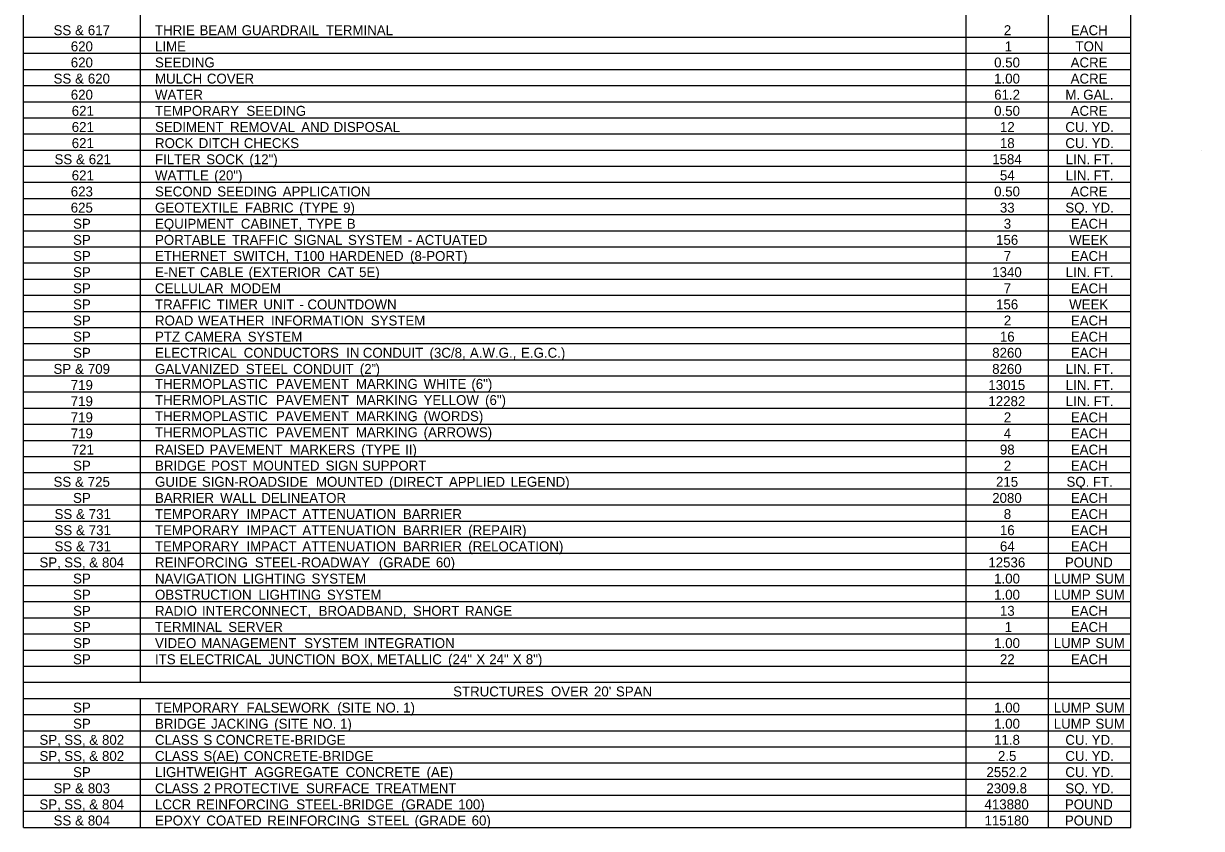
# Model space of a CAD drawing. Extents: x 107 to 7866, y 32 to 1473.
# Drawn here: x 6428 to 7140, y 67 to 553 of the extents above; entities that cross this region are included whole.
import ezdxf

# ---------------------------------------------------------------- set-up
doc = ezdxf.new("R2010")
doc.units = 0
doc.layers.add('Default', color=7, linetype='Continuous')

msp = doc.modelspace()

# ---------------------------------------------------------------- linework, layer by layer
at = {"layer": 'Default'}
for p, q in [((6427.83, 67.45), (6427.83, 1032.7)), ((6427.83, 67.45), (6427.83, 1032.7)), ((6498.52, 155.2), (6498.52, 1032.7)), ((6997.72, 67.45), (6997.72, 1032.7)), ((7047.45, 67.45), (7047.45, 1032.7)), ((7047.45, 155.2), (7047.45, 1032.7)), ((7097.17, 67.45), (7097.17, 1032.7)), ((6498.52, 340.45), (6498.52, 1003.45)), ((6997.72, 340.45), (6997.72, 1003.45)), ((6427.83, 545.2), (7097.17, 545.2)), ((6427.83, 535.45), (7097.17, 535.45)), ((6427.83, 525.7), (7097.17, 525.7)), ((6427.83, 515.95), (7097.17, 515.95)), ((6427.83, 506.2), (7097.17, 506.2)), ((6427.83, 496.45), (7097.17, 496.45)), ((6427.83, 486.7), (7097.17, 486.7)), ((6427.83, 476.95), (7097.17, 476.95)), ((7139.96, 476.49), (7139.96, 476.49)), ((6427.83, 467.2), (7097.17, 467.2)), ((6427.83, 457.45), (7097.17, 457.45)), ((6427.83, 447.7), (7097.17, 447.7)), ((6427.83, 437.95), (7097.17, 437.95)), ((6427.83, 428.2), (7097.17, 428.2)), ((6427.83, 418.45), (7097.17, 418.45)), ((6427.83, 408.7), (7097.17, 408.7)), ((6427.83, 398.95), (7097.17, 398.95)), ((6427.83, 389.2), (7097.17, 389.2)), ((6427.83, 379.45), (7097.17, 379.45)), ((6427.83, 369.7), (7097.17, 369.7)), ((6427.83, 359.95), (7097.17, 359.95)), ((6427.83, 350.2), (7097.17, 350.2)), ((6427.83, 340.45), (7097.17, 340.45)), ((6427.83, 330.7), (7097.17, 330.7)), ((6498.52, 330.7), (6997.72, 330.7)), ((6498.52, 301.45), (6498.52, 330.7)), ((6997.72, 330.7), (7097.17, 330.7)), ((6997.72, 155.2), (6997.72, 330.7)), ((6427.83, 320.95), (7097.17, 320.95)), ((6427.83, 311.2), (7097.17, 311.2)), ((6427.83, 301.45), (7097.17, 301.45)), ((6498.52, 155.2), (6498.52, 301.45)), ((6427.83, 291.7), (7097.17, 291.7)), ((6427.83, 281.95), (7097.17, 281.95)), ((6427.83, 272.2), (7097.17, 272.2)), ((6427.83, 262.45), (7097.17, 262.45)), ((6427.83, 252.7), (7097.17, 252.7)), ((6427.83, 242.95), (7097.17, 242.95)), ((6427.83, 233.2), (7097.17, 233.2)), ((6427.83, 223.45), (7097.17, 223.45)), ((6427.83, 213.7), (7097.17, 213.7)), ((6427.83, 203.95), (7097.17, 203.95)), ((6427.83, 194.2), (7097.17, 194.2)), ((6427.83, 184.45), (7097.17, 184.45)), ((6427.83, 174.7), (7097.17, 174.7)), ((6427.83, 164.95), (7097.17, 164.95)), ((6427.83, 155.2), (7097.17, 155.2)), ((7047.45, 155.2), (7097.17, 155.2)), ((6427.83, 145.45), (7097.17, 145.45)), ((6427.83, 145.45), (7097.17, 145.45)), ((6498.52, 67.45), (6498.52, 145.45)), ((6498.52, 67.45), (6498.52, 145.45)), ((6997.72, 67.45), (6997.72, 145.45)), ((7047.45, 67.45), (7047.45, 145.45)), ((6427.83, 135.7), (7097.17, 135.7)), ((6427.83, 125.95), (7097.17, 125.95)), ((6427.83, 116.2), (7097.17, 116.2)), ((6427.83, 106.45), (7097.17, 106.45)), ((6427.83, 96.7), (7097.17, 96.7)), ((6427.83, 86.95), (7097.17, 86.95)), ((6427.83, 77.2), (7097.17, 77.2)), ((6427.83, 67.45), (7097.17, 67.45))]:
    msp.add_line(p, q, dxfattribs=at)

# ---------------------------------------------------------------- texts
for s, p in [('SS', (6445.97, 546.4)), (' &', (6456.72, 546.4)), (' 617', (6464.45, 546.4)), ('THRIE', (6507.3, 546.4)), (' BEAM', (6532, 546.4)), (' GUARDRAIL', (6557.46, 546.4)), (' TERMINAL', (6608.4, 546.4)), ('2', (7020.47, 546.4)), ('EACH', (7061, 546.4)), ('620', (6456.39, 536.65)), ('LIME', (6507.3, 536.65)), ('1', (7021.02, 536.65)), ('TON', (7063.8, 536.65)), ('620', (6456.39, 526.9)), ('SEEDING', (6507.3, 526.9)), ('0.50', (7014.63, 526.9)), ('ACRE', (7060.88, 526.9)), ('SS', (6445.99, 517.15)), (' &', (6456.73, 517.15)), (' 620', (6464.46, 517.15)), ('MULCH', (6507.3, 517.15)), (' COVER', (6536.43, 517.15)), ('1.00', (7014.63, 517.15)), ('ACRE', (7060.88, 517.15)), ('620', (6456.39, 507.4)), ('WATER', (6507.3, 507.4)), ('61.2', (7014.65, 507.4)), ('M.', (7057.67, 507.4)), (' GAL.', (7066.25, 507.4)), ('621', (6456.96, 497.65)), ('TEMPORARY', (6507.3, 497.65)), (' SEEDING', (6560.34, 497.65)), ('0.50', (7014.63, 497.65)), ('ACRE', (7060.88, 497.65)), ('621', (6456.96, 487.9)), ('SEDIMENT', (6507.3, 487.9)), (' REMOVAL', (6550.45, 487.9)), (' AND', (6593.48, 487.9)), (' DISPOSAL', (6613.06, 487.9)), ('12', (7018.14, 487.9)), ('CU.', (7057.67, 487.9)), (' YD.', (7071.37, 487.9)), ('621', (6456.96, 478.15)), ('ROCK', (6507.3, 478.15)), (' DITCH', (6531.5, 478.15)), (' CHECKS', (6558.77, 478.15)), ('18', (7018.11, 478.15)), ('CU.', (7057.67, 478.15)), (' YD.', (7071.37, 478.15)), ('SS', (6446.56, 468.4)), (' &', (6457.3, 468.4)), (' 621', (6465.03, 468.4)), ('FILTER', (6507.3, 468.4)), (' SOCK', (6536.06, 468.4)), (' (12")', (6562.13, 468.4)), ('1584', (7013.47, 468.4)), ('LIN.', (7057.9, 468.4)), (' FT.', (7072.54, 468.4)), ('621', (6456.96, 458.65)), ('WATTLE', (6507.3, 458.65)), (' (20")', (6540.85, 458.65)), ('54', (7018.13, 458.65)), ('LIN.', (7057.9, 458.65)), (' FT.', (7072.54, 458.65)), ('623', (6456.38, 448.9)), ('SECOND', (6507.3, 448.9)), (' SEEDING', (6542.72, 448.9)), (' APPLICATION', (6582.26, 448.9)), ('0.50', (7014.63, 448.9)), ('ACRE', (7060.88, 448.9)), ('625', (6456.35, 439.15)), ('GEOTEXTILE', (6507.3, 439.15)), (' FABRIC', (6559.49, 439.15)), (' (TYPE', (6592.23, 439.15)), (' 9)', (6618.8, 439.15)), ('33', (7018.11, 439.15)), ('SQ.', (7057.67, 439.15)), (' YD.', (7071.38, 439.15)), ('SP', (6457.77, 429.4)), ('EQUIPMENT', (6507.3, 429.4)), (' CABINET,', (6556.97, 429.4)), (' TYPE', (6597.22, 429.4)), (' B', (6621, 429.4)), ('3', (7020.44, 429.4)), ('EACH', (7061, 429.4)), ('SP', (6457.77, 419.65)), ('PORTABLE', (6507.3, 419.65)), (' TRAFFIC', (6551.58, 419.65)), (' SIGNAL', (6588.97, 419.65)), (' SYSTEM', (6621.75, 419.65)), (' -', (6657.92, 419.65)), (' ACTUATED', (6662.78, 419.65)), ('156', (7015.78, 419.65)), ('WEEK', (7059.97, 419.65)), ('SP', (6457.77, 409.9)), ('ETHERNET', (6507.3, 409.9)), (' SWITCH,', (6552.31, 409.9)), (' T100', (6589.29, 409.9)), (' HARDENED', (6610.32, 409.9)), (' (8-PORT)', (6659.25, 409.9)), ('7', (7020.44, 409.9)), ('EACH', (7061, 409.9)), ('SP', (6457.77, 400.15)), ('E-NET', (6507.3, 400.15)), (' CABLE', (6532.28, 400.15)), (' (EXTERIOR', (6561.65, 400.15)), (' CAT', (6609.51, 400.15)), (' 5E)', (6628.44, 400.15)), ('1340', (7013.46, 400.15)), ('LIN.', (7057.9, 400.15)), (' FT.', (7072.54, 400.15)), ('SP', (6457.77, 390.4)), ('CELLULAR', (6507.3, 390.4)), (' MODEM', (6550.51, 390.4)), ('7', (7020.44, 390.4)), ('EACH', (7061, 390.4)), ('SP', (6457.77, 380.65)), ('TRAFFIC', (6507.3, 380.65)), (' TIMER', (6542.36, 380.65)), (' UNIT', (6570.65, 380.65)), (' COUNTDOWN', (6597.23, 380.65)), ('156', (7015.78, 380.65)), ('WEEK', (7059.97, 380.65)), (' -', (6592.37, 380.65)), ('SP', (6457.77, 370.9)), ('ROAD', (6507.3, 370.9)), (' WEATHER', (6531.07, 370.9)), (' INFORMATION', (6575.21, 370.9)), (' SYSTEM', (6635.53, 370.9)), ('2', (7020.47, 370.9)), ('EACH', (7061, 370.9)), ('SP', (6457.77, 361.15)), ('PTZ', (6507.3, 361.15)), (' CAMERA', (6522.92, 361.15)), (' SYSTEM', (6561.14, 361.15)), ('16', (7018.11, 361.15)), ('EACH', (7061, 361.15)), ('SP', (6457.77, 351.4)), ('ELECTRICAL', (6507.3, 351.4)), (' CONDUCTORS', (6558.71, 351.4)), (' IN', (6620.69, 351.4)), (' CONDUIT', (6630.71, 351.4)), (' (3C/8,', (6671.06, 351.4)), (' A.W.G.,', (6695.46, 351.4)), (' E.G.C.)', (6726.38, 351.4)), ('8260', (7013.46, 351.4)), ('EACH', (7061, 351.4)), ('SP', (6445.93, 341.65)), (' &', (6456.75, 341.65)), (' 709', (6464.48, 341.65)), ('GALVANIZED', (6507.3, 341.65)), (' STEEL', (6559.96, 341.65)), (' CONDUIT', (6588.55, 341.65)), (' (2', (6628.9, 341.65)), ('”', (6638.23, 341.65)), (')', (6640.65, 341.65)), ('8260', (7013.46, 341.65)), ('LIN.', (7057.9, 341.65)), (' FT.', (7072.54, 341.65)), ('719', (6456.37, 331.9)), ('THERMOPLASTIC', (6507.3, 332.58)), (' PAVEMENT', (6578.23, 332.58)), (' MARKING', (6626.52, 332.58)), (' WHITE', (6667.45, 332.58)), (' (6")', (6696.34, 332.58)), ('13015', (7011.1, 331.9)), ('LIN.', (7057.9, 331.9)), (' FT.', (7072.54, 331.9)), ('719', (6456.37, 322.15)), ('THERMOPLASTIC', (6507.3, 322.83)), (' PAVEMENT', (6578.23, 322.83)), (' MARKING', (6626.52, 322.83)), (' YELLOW', (6667.45, 322.83)), (' (6")', (6704.62, 322.83)), ('12282', (7011.15, 322.15)), ('LIN.', (7057.9, 322.15)), (' FT.', (7072.54, 322.15)), ('719', (6456.37, 312.4)), ('THERMOPLASTIC', (6507.3, 313.08)), (' PAVEMENT', (6578.23, 313.08)), (' MARKING', (6626.52, 313.08)), (' (WORDS)', (6667.45, 313.08)), ('2', (7020.47, 312.4)), ('EACH', (7061, 312.4)), ('719', (6456.37, 302.65)), ('THERMOPLASTIC', (6507.3, 303.33)), (' PAVEMENT', (6578.23, 303.33)), (' MARKING', (6626.52, 303.33)), (' (ARROWS)', (6667.45, 303.33)), ('4', (7020.46, 302.65)), ('EACH', (7061, 302.65)), (' (TYPE', (6629.7, 292.9)), (' II)', (6656.27, 292.9)), ('721', (6456.96, 292.9)), ('RAISED', (6507.3, 292.9)), (' PAVEMENT', (6538.06, 292.9)), (' MARKERS', (6586.35, 292.9)), ('98', (7018.11, 292.9)), ('EACH', (7061, 292.9)), ('SP', (6457.77, 283.15)), ('BRIDGE', (6507.3, 283.15)), (' POST', (6538.99, 283.15)), (' MOUNTED', (6563.98, 283.15)), (' SIGN', (6608.24, 283.15)), (' SUPPORT', (6630.38, 283.15)), ('2', (7020.47, 283.15)), ('EACH', (7061, 283.15)), ('SS', (6445.95, 273.4)), (' &', (6456.7, 273.4)), (' 725', (6464.43, 273.4)), ('GUIDE', (6507.3, 273.4)), (' SIGN-ROADSIDE', (6533.4, 273.4)), (' MOUNTED', (6602.36, 273.4)), (' (DIRECT', (6646.62, 273.4)), (' APPLIED', (6682.78, 273.4)), (' LEGEND)', (6720.07, 273.4)), ('215', (7015.76, 273.4)), ('SQ.', (7058.37, 273.4)), (' FT.', (7072.08, 273.4)), ('SP', (6457.77, 263.65)), ('BARRIER', (6507.3, 263.65)), (' WALL', (6544.45, 263.65)), (' DELINEATOR', (6569.31, 263.65)), ('2080', (7013.46, 263.65)), ('EACH', (7061, 263.65)), ('SS', (6446.56, 253.9)), (' &', (6457.3, 253.9)), (' 731', (6465.03, 253.9)), ('TEMPORARY', (6507.3, 253.9)), (' IMPACT', (6560.34, 253.9)), (' ATTENUATION', (6594.17, 253.9)), (' BARRIER', (6654.97, 253.9)), ('8', (7020.44, 253.9)), ('EACH', (7061, 253.9)), ('SS', (6446.56, 244.15)), (' &', (6457.3, 244.15)), (' 731', (6465.03, 244.15)), ('TEMPORARY', (6507.3, 244.15)), (' IMPACT', (6560.34, 244.15)), (' ATTENUATION', (6594.17, 244.15)), (' BARRIER', (6654.97, 244.15)), (' (REPAIR)', (6694.46, 244.15)), ('16', (7018.11, 244.15)), ('EACH', (7061, 244.15)), ('SS', (6446.56, 234.4)), (' &', (6457.3, 234.4)), (' 731', (6465.03, 234.4)), ('TEMPORARY', (6507.3, 234.4)), (' IMPACT', (6560.34, 234.4)), (' ATTENUATION', (6594.17, 234.4)), (' BARRIER', (6654.97, 234.4)), (' (RELOCATION)', (6694.46, 234.4)), ('64', (7018.13, 234.4)), ('EACH', (7061, 234.4)), ('SP,', (6437.43, 224.65)), (' SS,', (6450.2, 224.65)), (' &', (6465.29, 224.65)), (' 804', (6473.02, 224.65)), ('REINFORCING', (6507.3, 224.65)), (' STEEL-ROADWAY', (6565.46, 224.65)), (' (GRADE', (6640.39, 224.65)), (' 60)', (6674.88, 224.65)), ('12536', (7011.12, 224.65)), ('POUND', (7057.39, 224.65)), ('SP', (6457.77, 214.9)), ('NAVIGATION', (6507.3, 214.9)), (' LIGHTING', (6558.32, 214.9)), (' SYSTEM', (6599.71, 214.9)), ('1.00', (7014.63, 214.9)), ('LUMP', (7050.68, 214.9)), (' SUM', (7073.61, 214.9)), ('SP', (6457.77, 205.15)), ('OBSTRUCTION', (6507.3, 205.15)), (' LIGHTING', (6567.63, 205.15)), (' SYSTEM', (6609.02, 205.15)), ('1.00', (7014.63, 205.15)), ('LUMP', (7050.68, 205.15)), (' SUM', (7073.61, 205.15)), ('SP', (6457.77, 195.4)), ('RADIO', (6507.3, 195.4)), (' INTERCONNECT,', (6533.47, 195.4)), (' BROADBAND,', (6603.99, 195.4)), (' SHORT', (6661.01, 195.4)), (' RANGE', (6692.52, 195.4)), ('13', (7018.11, 195.4)), ('EACH', (7061, 195.4)), ('SP', (6457.77, 185.65)), ('TERMINAL', (6507.3, 185.65)), (' SERVER', (6549.39, 185.65)), ('1', (7021.02, 185.65)), ('EACH', (7061, 185.65)), ('SP', (6457.77, 175.9)), ('VIDEO', (6507.3, 175.9)), (' MANAGEMENT', (6533.01, 175.9)), (' SYSTEM', (6595.26, 175.9)), (' INTEGRATION', (6631.43, 175.9)), ('1.00', (7014.63, 175.9)), ('LUMP', (7050.68, 175.9)), (' SUM', (7073.61, 175.9)), ('SP', (6457.77, 166.15)), ('ITS', (6507.3, 166.15)), (' ELECTRICAL', (6519.9, 166.15)), (' JUNCTION', (6573.64, 166.15)), (' BOX,', (6617.67, 166.15)), (' METALLIC', (6639.29, 166.15)), (' (24"', (6682.27, 166.15)), (' X', (6699.3, 166.15)), (' 24"', (6707.16, 166.15)), (' X', (6721.39, 166.15)), (' 8")', (6729.26, 166.15)), ('22', (7018.14, 166.15)), ('EACH', (7061, 166.15)), ('STRUCTURES', (6687.54, 146.65)), (' OVER', (6744.43, 146.65)), (" 20'", (6770.47, 146.65)), (' SPAN', (6783.75, 146.65)), ('SP', (6457.77, 136.9)), ('TEMPORARY', (6507.3, 136.9)), (' FALSEWORK', (6560.34, 136.9)), (' (SITE', (6615.29, 136.9)), (' NO.', (6638.6, 136.9)), (' 1)', (6655.1, 136.9)), ('1.00', (7014.63, 136.9)), ('LUMP', (7050.68, 136.9)), (' SUM', (7073.61, 136.9)), ('SP', (6457.77, 127.15)), ('BRIDGE', (6507.3, 127.15)), (' JACKING', (6538.99, 127.15)), (' (SITE', (6577.13, 127.15)), (' NO.', (6600.44, 127.15)), (' 1)', (6616.94, 127.15)), ('1.00', (7014.63, 127.15)), ('LUMP', (7050.68, 127.15)), (' SUM', (7073.61, 127.15)), ('SP,', (6437.45, 117.4)), (' SS,', (6450.22, 117.4)), (' &', (6465.31, 117.4)), (' 802', (6473.04, 117.4)), ('CLASS', (6507.3, 117.4)), (' S', (6534.35, 117.4)), (' CONCRETE-BRIDGE', (6541.83, 117.4)), ('11.8', (7014.61, 117.4)), ('CU.', (7057.67, 117.4)), (' YD.', (7071.37, 117.4)), (' S(AE)', (6534.35, 107.65)), ('SP,', (6437.45, 107.65)), (' SS,', (6450.22, 107.65)), (' &', (6465.31, 107.65)), (' 802', (6473.04, 107.65)), ('CLASS', (6507.3, 107.65)), (' CONCRETE-BRIDGE', (6558.73, 107.65)), ('2.5', (7016.93, 107.65)), ('CU.', (7057.67, 107.65)), (' YD.', (7071.37, 107.65)), ('SP', (6457.77, 97.9)), ('LIGHTWEIGHT', (6507.3, 97.9)), (' AGGREGATE', (6565.34, 97.9)), (' CONCRETE', (6620.33, 97.9)), (' (AE)', (6669.26, 97.9)), ('2552.2', (7009.99, 97.9)), ('CU.', (7057.67, 97.9)), (' YD.', (7071.37, 97.9)), ('SP', (6445.94, 88.15)), (' &', (6456.76, 88.15)), (' 803', (6464.49, 88.15)), ('CLASS', (6507.3, 88.15)), (' 2', (6534.35, 88.15)), (' PROTECTIVE', (6540.89, 88.15)), (' SURFACE', (6596.35, 88.15)), (' TREATMENT', (6638.29, 88.15)), ('2309.8', (7009.95, 88.15)), ('SQ.', (7057.67, 88.15)), (' YD.', (7071.38, 88.15)), ('SP,', (6437.43, 78.4)), (' SS,', (6450.2, 78.4)), (' &', (6465.29, 78.4)), (' 804', (6473.02, 78.4)), ('LCCR', (6507.3, 78.4)), (' REINFORCING', (6530.01, 78.4)), (' STEEL-BRIDGE', (6590.5, 78.4)), (' (GRADE', (6653.87, 78.4)), (' 100)', (6688.36, 78.4)), ('413880', (7008.8, 78.4)), ('POUND', (7057.39, 78.4)), ('SS', (6445.99, 68.65)), (' &', (6456.74, 68.65)), (' 804', (6464.46, 68.65)), ('EPOXY', (6507.3, 68.65)), (' COATED', (6536.12, 68.65)), (' REINFORCING', (6572.94, 68.65)), (' STEEL', (6633.43, 68.65)), (' (GRADE', (6662.02, 68.65)), (' 60)', (6696.51, 68.65)), ('115180', (7008.8, 68.65)), ('POUND', (7057.39, 68.65))]:
    msp.add_text(s, height=6, dxfattribs=at).set_placement(p)

doc.saveas('drawing.dxf')
